(* Logix 5000 project; controller Electronic_Displays vendor 1 type 14 code 65 rev 17.4; software revision 17.01; part 7 of 9 *)
(* tags used below, declared in another part *)
   ENVariable2Message : BOOL;   // 0 = don't setup variable 1 = setup variable
   ENVariable3Message : BOOL;   // 0 = don't setup variable 1 = setup variable
   ENVariable4Message : BOOL;   // 0 = don't setup variable 1 = setup variable
   DN : BOOL;   // Instruction Interface Done Bit
   ER : BOOL;   // Instruction Interface Error Bit
   map_SignOutput : SINT[496];   // Ethernet/IP LEDSIGN.O Data I/O Mapping
   Packet1Sent : STRING;   // The actual packet sent to the sign (Packet1)
   Packet2Sent : STRING;   // The actual packet sent to the sign (Packet2)
   Packet3Sent : STRING;   // The actual packet sent to the sign (Packet3)
   SEQ : DINT;   // Sequence Number
   InCycle : BOOL;   // Incycle
   Error : BOOL;   // Error
   Done : BOOL;   // Done
   SignETX : STRING;   // DO NOT EDIT = ^C
   SignSOH : STRING;   // DO NOT EDIT = ^A
   SignAddress : STRING;
   SignSTX : STRING;   // DO NOT EDIT = ^B
   SignVariable4 : STRING;
   SignVariable3 : STRING;
   SignVariable2 : STRING;
   SignSetMemoryCommand : STRING;   // DO NOT EDIT = SM
   SignCommandCode : STRING;   // DO NOT EDIT = C
   SignSizeVariableCommand : STRING;   // DO NOT EDIT = 0010 (16 bytes of memory) enough for 16 characters
   SignFileVariableCommand : STRING;   // DO NOT EDIT = V
   TotalPacketCount : DINT[7];   // Total Character Count
   Select : DINT;   // Packet Array Select
   PacketMax : DINT;   // Max Packet Count
   Packet3Offset : DINT;
   Packet2Offset : DINT;
   Packet1Offset : DINT;
   Packet : STRING[7];   // Packet Array to send to sign
(* SetupSignVariables, continued *)

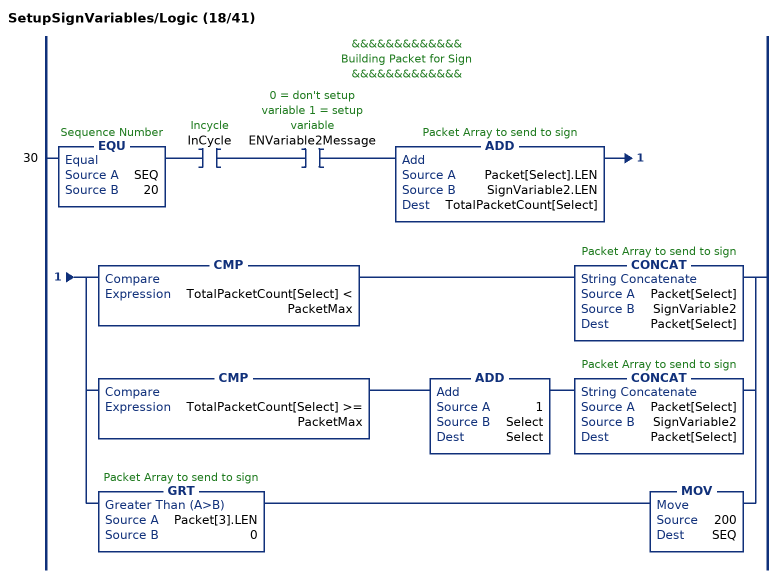
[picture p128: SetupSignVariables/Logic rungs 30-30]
   // &&&&&&&&&&&&&
   // Building Packet for Sign
   // &&&&&&&&&&&&&
   30: EQU(SEQ,20)XIC(InCycle)XIC(ENVariable2Message)ADD(Packet[Select].LEN,SignVariable2.LEN,TotalPacketCount[Select])[CMP(TotalPacketCount[Select] < PacketMax) CONCAT(Packet[Select],SignVariable2,Packet[Select]) ,CMP(TotalPacketCount[Select] >= PacketMax) ADD(1,Select,Select) CONCAT(Packet[Select],SignVariable2,Packet[Select]) ,GRT(Packet[3].LEN,0) MOV(200,SEQ) ];
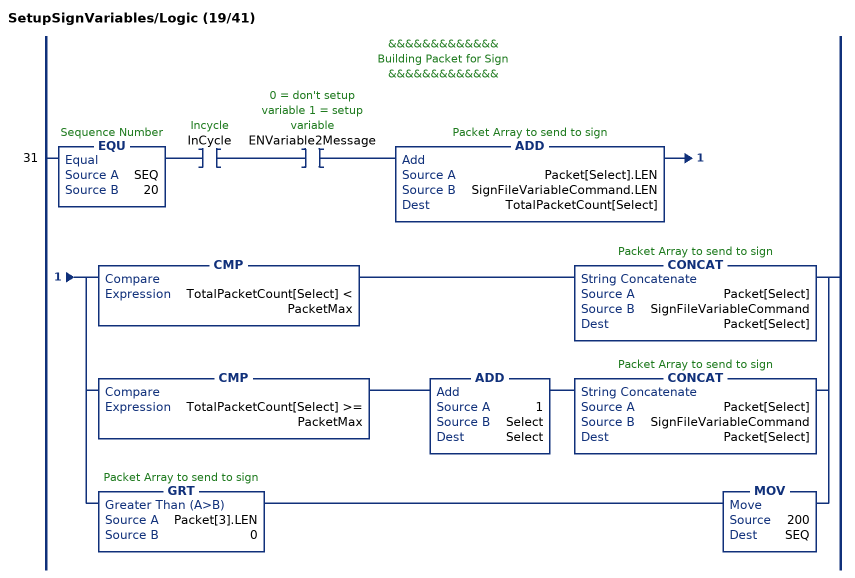
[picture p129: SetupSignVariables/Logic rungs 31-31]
   // &&&&&&&&&&&&&
   // Building Packet for Sign
   // &&&&&&&&&&&&&
   31: EQU(SEQ,20)XIC(InCycle)XIC(ENVariable2Message)ADD(Packet[Select].LEN,SignFileVariableCommand.LEN,TotalPacketCount[Select])[CMP(TotalPacketCount[Select] < PacketMax) CONCAT(Packet[Select],SignFileVariableCommand,Packet[Select]) ,CMP(TotalPacketCount[Select] >= PacketMax) ADD(1,Select,Select) CONCAT(Packet[Select],SignFileVariableCommand,Packet[Select]) ,GRT(Packet[3].LEN,0) MOV(200,SEQ) ];
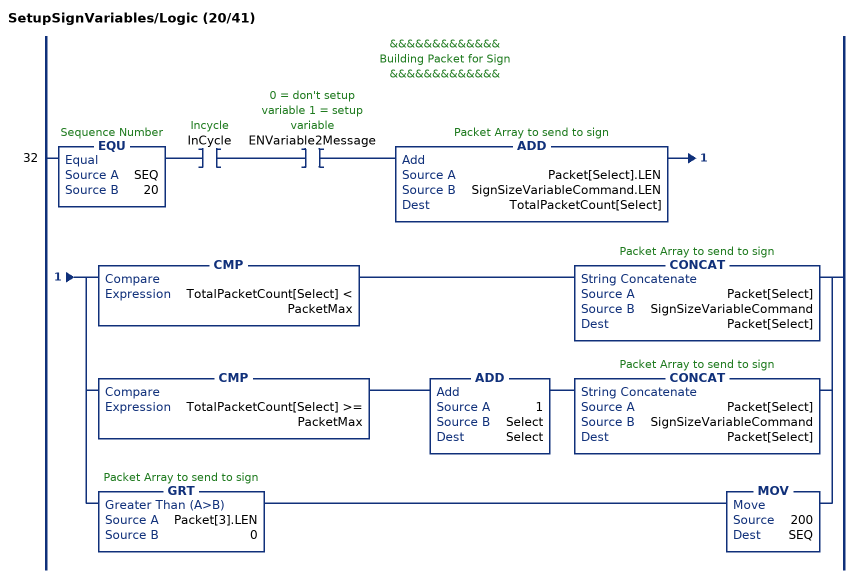
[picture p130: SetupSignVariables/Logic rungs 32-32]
   // &&&&&&&&&&&&&
   // Building Packet for Sign
   // &&&&&&&&&&&&&
   32: EQU(SEQ,20)XIC(InCycle)XIC(ENVariable2Message)ADD(Packet[Select].LEN,SignSizeVariableCommand.LEN,TotalPacketCount[Select])[CMP(TotalPacketCount[Select] < PacketMax) CONCAT(Packet[Select],SignSizeVariableCommand,Packet[Select]) ,CMP(TotalPacketCount[Select] >= PacketMax) ADD(1,Select,Select) CONCAT(Packet[Select],SignSizeVariableCommand,Packet[Select]) ,GRT(Packet[3].LEN,0) MOV(200,SEQ) ];
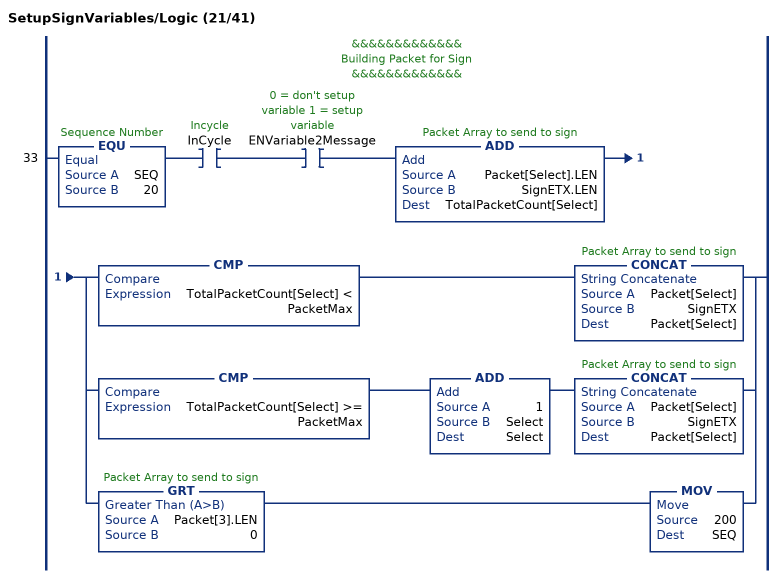
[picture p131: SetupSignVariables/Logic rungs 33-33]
   // &&&&&&&&&&&&&
   // Building Packet for Sign
   // &&&&&&&&&&&&&
   33: EQU(SEQ,20)XIC(InCycle)XIC(ENVariable2Message)ADD(Packet[Select].LEN,SignETX.LEN,TotalPacketCount[Select])[CMP(TotalPacketCount[Select] < PacketMax) CONCAT(Packet[Select],SignETX,Packet[Select]) ,CMP(TotalPacketCount[Select] >= PacketMax) ADD(1,Select,Select) CONCAT(Packet[Select],SignETX,Packet[Select]) ,GRT(Packet[3].LEN,0) MOV(200,SEQ) ];
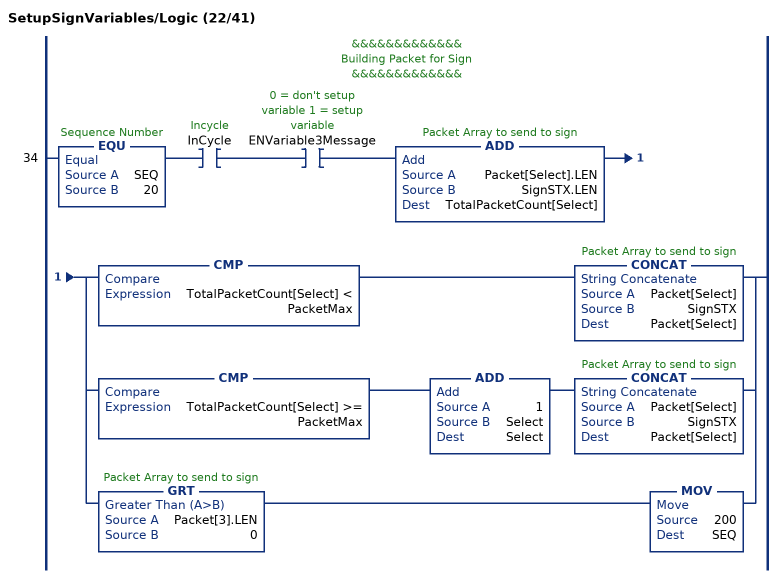
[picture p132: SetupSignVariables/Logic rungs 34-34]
   // &&&&&&&&&&&&&
   // Building Packet for Sign
   // &&&&&&&&&&&&&
   34: EQU(SEQ,20)XIC(InCycle)XIC(ENVariable3Message)ADD(Packet[Select].LEN,SignSTX.LEN,TotalPacketCount[Select])[CMP(TotalPacketCount[Select] < PacketMax) CONCAT(Packet[Select],SignSTX,Packet[Select]) ,CMP(TotalPacketCount[Select] >= PacketMax) ADD(1,Select,Select) CONCAT(Packet[Select],SignSTX,Packet[Select]) ,GRT(Packet[3].LEN,0) MOV(200,SEQ) ];
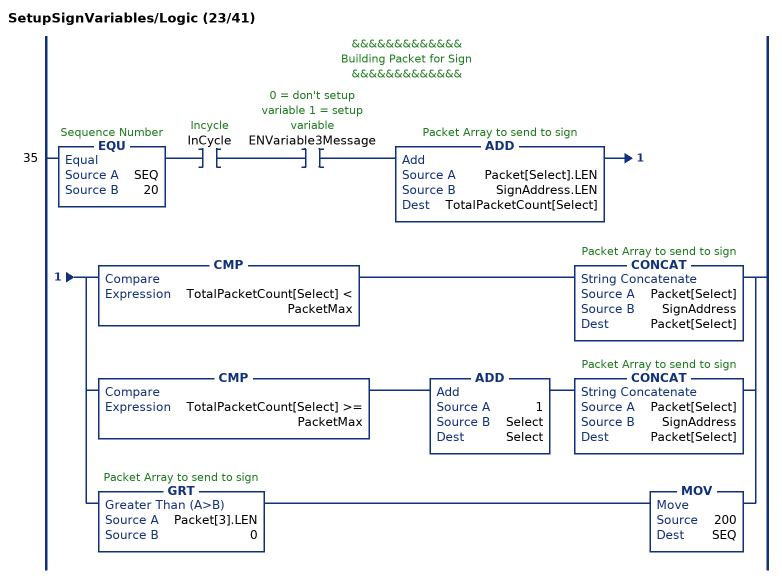
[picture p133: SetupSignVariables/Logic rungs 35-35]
   // &&&&&&&&&&&&&
   // Building Packet for Sign
   // &&&&&&&&&&&&&
   35: EQU(SEQ,20)XIC(InCycle)XIC(ENVariable3Message)ADD(Packet[Select].LEN,SignAddress.LEN,TotalPacketCount[Select])[CMP(TotalPacketCount[Select] < PacketMax) CONCAT(Packet[Select],SignAddress,Packet[Select]) ,CMP(TotalPacketCount[Select] >= PacketMax) ADD(1,Select,Select) CONCAT(Packet[Select],SignAddress,Packet[Select]) ,GRT(Packet[3].LEN,0) MOV(200,SEQ) ];
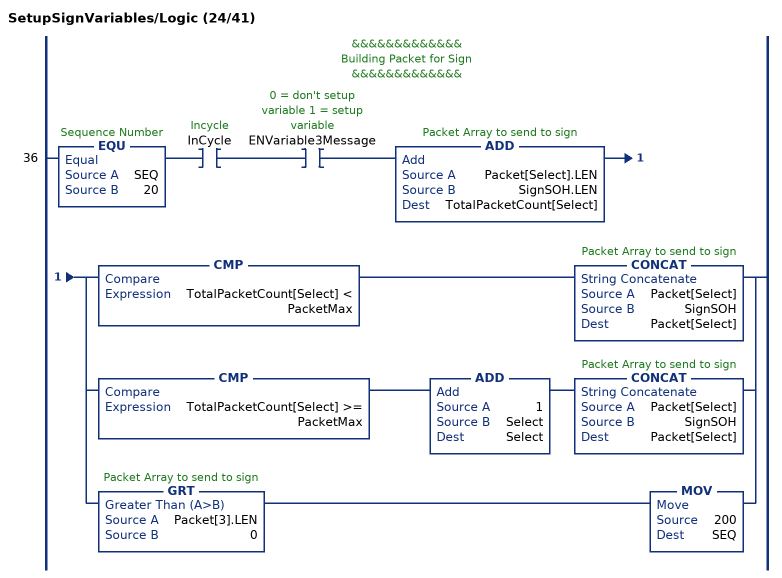
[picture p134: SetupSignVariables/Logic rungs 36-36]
   // &&&&&&&&&&&&&
   // Building Packet for Sign
   // &&&&&&&&&&&&&
   36: EQU(SEQ,20)XIC(InCycle)XIC(ENVariable3Message)ADD(Packet[Select].LEN,SignSOH.LEN,TotalPacketCount[Select])[CMP(TotalPacketCount[Select] < PacketMax) CONCAT(Packet[Select],SignSOH,Packet[Select]) ,CMP(TotalPacketCount[Select] >= PacketMax) ADD(1,Select,Select) CONCAT(Packet[Select],SignSOH,Packet[Select]) ,GRT(Packet[3].LEN,0) MOV(200,SEQ) ];
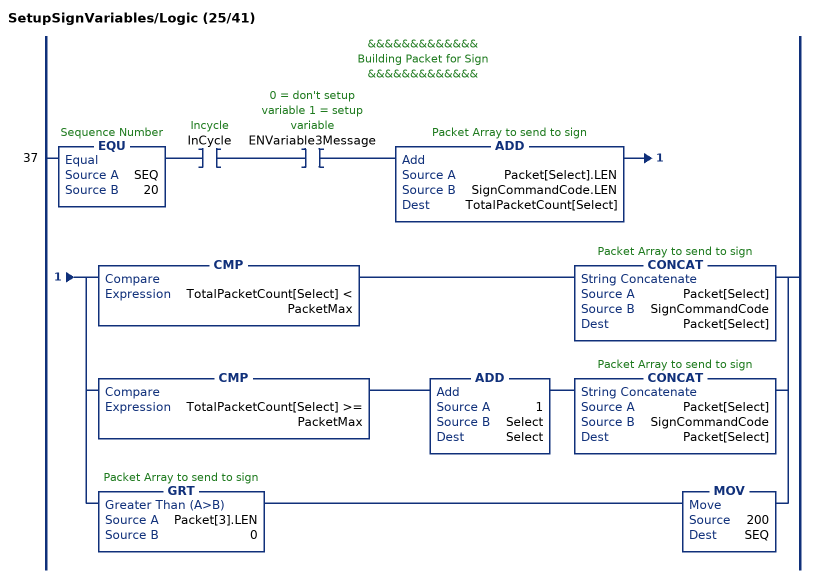
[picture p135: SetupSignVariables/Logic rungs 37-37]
   // &&&&&&&&&&&&&
   // Building Packet for Sign
   // &&&&&&&&&&&&&
   37: EQU(SEQ,20)XIC(InCycle)XIC(ENVariable3Message)ADD(Packet[Select].LEN,SignCommandCode.LEN,TotalPacketCount[Select])[CMP(TotalPacketCount[Select] < PacketMax) CONCAT(Packet[Select],SignCommandCode,Packet[Select]) ,CMP(TotalPacketCount[Select] >= PacketMax) ADD(1,Select,Select) CONCAT(Packet[Select],SignCommandCode,Packet[Select]) ,GRT(Packet[3].LEN,0) MOV(200,SEQ) ];
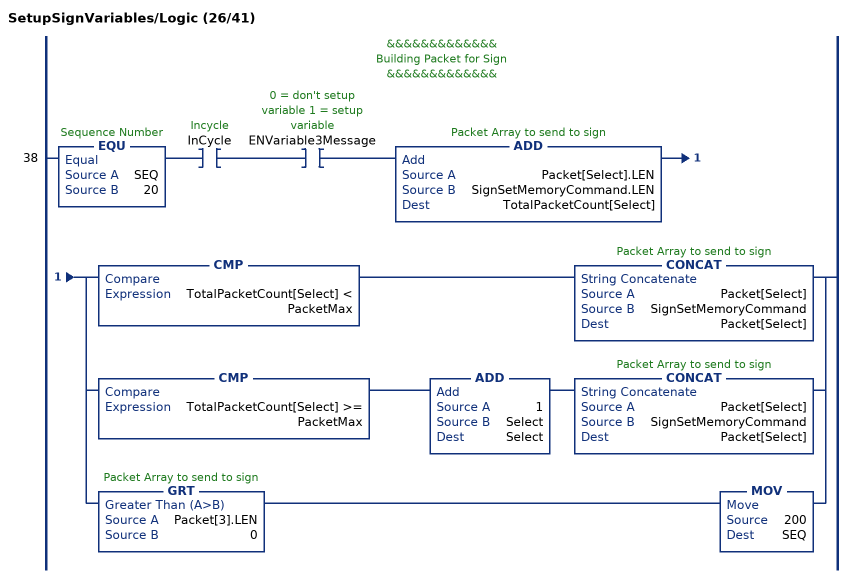
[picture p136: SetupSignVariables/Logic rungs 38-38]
   // &&&&&&&&&&&&&
   // Building Packet for Sign
   // &&&&&&&&&&&&&
   38: EQU(SEQ,20)XIC(InCycle)XIC(ENVariable3Message)ADD(Packet[Select].LEN,SignSetMemoryCommand.LEN,TotalPacketCount[Select])[CMP(TotalPacketCount[Select] < PacketMax) CONCAT(Packet[Select],SignSetMemoryCommand,Packet[Select]) ,CMP(TotalPacketCount[Select] >= PacketMax) ADD(1,Select,Select) CONCAT(Packet[Select],SignSetMemoryCommand,Packet[Select]) ,GRT(Packet[3].LEN,0) MOV(200,SEQ) ];
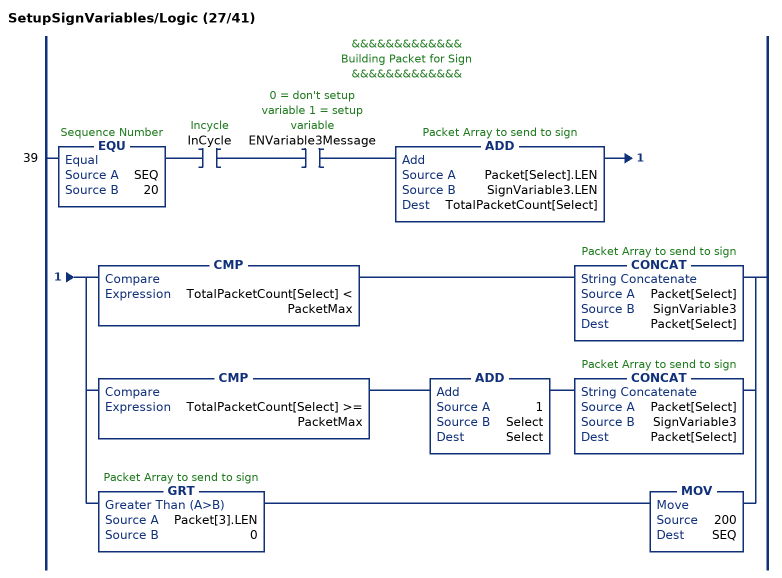
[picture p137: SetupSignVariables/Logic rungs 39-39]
   // &&&&&&&&&&&&&
   // Building Packet for Sign
   // &&&&&&&&&&&&&
   39: EQU(SEQ,20)XIC(InCycle)XIC(ENVariable3Message)ADD(Packet[Select].LEN,SignVariable3.LEN,TotalPacketCount[Select])[CMP(TotalPacketCount[Select] < PacketMax) CONCAT(Packet[Select],SignVariable3,Packet[Select]) ,CMP(TotalPacketCount[Select] >= PacketMax) ADD(1,Select,Select) CONCAT(Packet[Select],SignVariable3,Packet[Select]) ,GRT(Packet[3].LEN,0) MOV(200,SEQ) ];
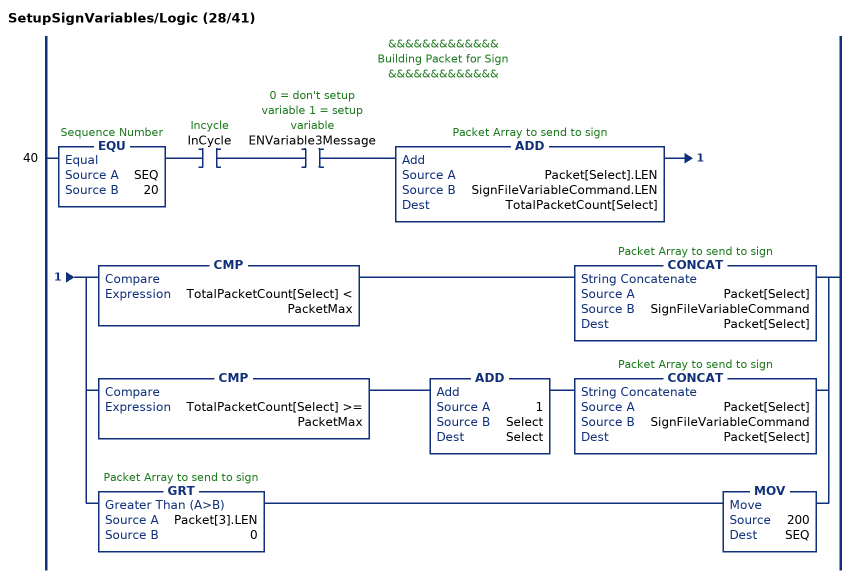
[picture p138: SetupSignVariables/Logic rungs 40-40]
   // &&&&&&&&&&&&&
   // Building Packet for Sign
   // &&&&&&&&&&&&&
   40: EQU(SEQ,20)XIC(InCycle)XIC(ENVariable3Message)ADD(Packet[Select].LEN,SignFileVariableCommand.LEN,TotalPacketCount[Select])[CMP(TotalPacketCount[Select] < PacketMax) CONCAT(Packet[Select],SignFileVariableCommand,Packet[Select]) ,CMP(TotalPacketCount[Select] >= PacketMax) ADD(1,Select,Select) CONCAT(Packet[Select],SignFileVariableCommand,Packet[Select]) ,GRT(Packet[3].LEN,0) MOV(200,SEQ) ];
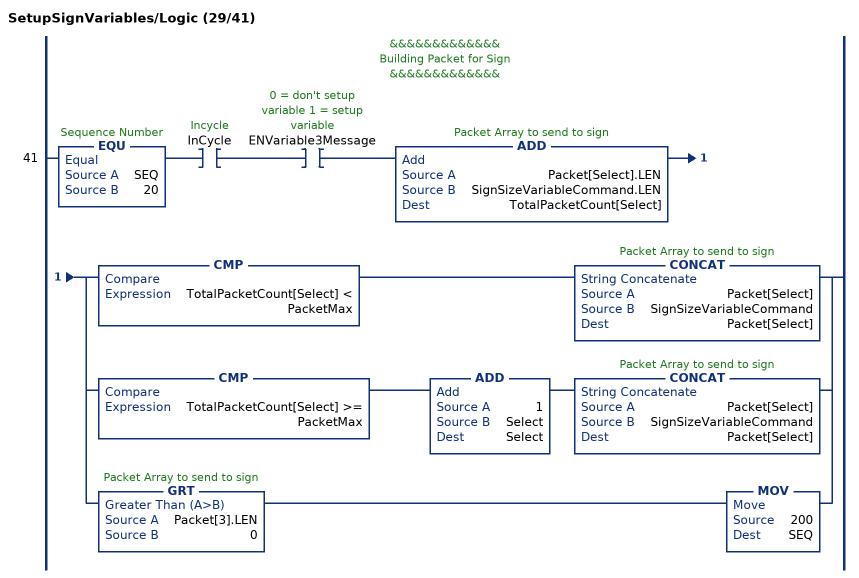
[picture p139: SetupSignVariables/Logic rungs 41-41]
   // &&&&&&&&&&&&&
   // Building Packet for Sign
   // &&&&&&&&&&&&&
   41: EQU(SEQ,20)XIC(InCycle)XIC(ENVariable3Message)ADD(Packet[Select].LEN,SignSizeVariableCommand.LEN,TotalPacketCount[Select])[CMP(TotalPacketCount[Select] < PacketMax) CONCAT(Packet[Select],SignSizeVariableCommand,Packet[Select]) ,CMP(TotalPacketCount[Select] >= PacketMax) ADD(1,Select,Select) CONCAT(Packet[Select],SignSizeVariableCommand,Packet[Select]) ,GRT(Packet[3].LEN,0) MOV(200,SEQ) ];
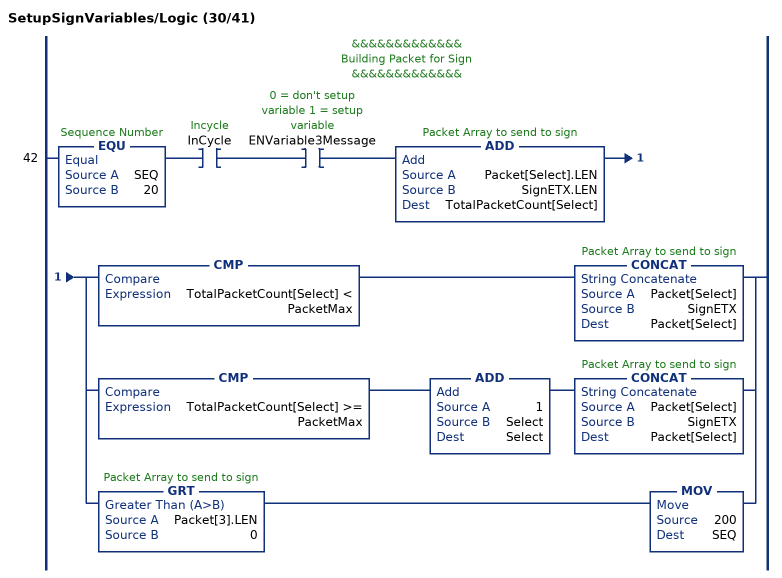
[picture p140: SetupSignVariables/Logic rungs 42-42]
   // &&&&&&&&&&&&&
   // Building Packet for Sign
   // &&&&&&&&&&&&&
   42: EQU(SEQ,20)XIC(InCycle)XIC(ENVariable3Message)ADD(Packet[Select].LEN,SignETX.LEN,TotalPacketCount[Select])[CMP(TotalPacketCount[Select] < PacketMax) CONCAT(Packet[Select],SignETX,Packet[Select]) ,CMP(TotalPacketCount[Select] >= PacketMax) ADD(1,Select,Select) CONCAT(Packet[Select],SignETX,Packet[Select]) ,GRT(Packet[3].LEN,0) MOV(200,SEQ) ];
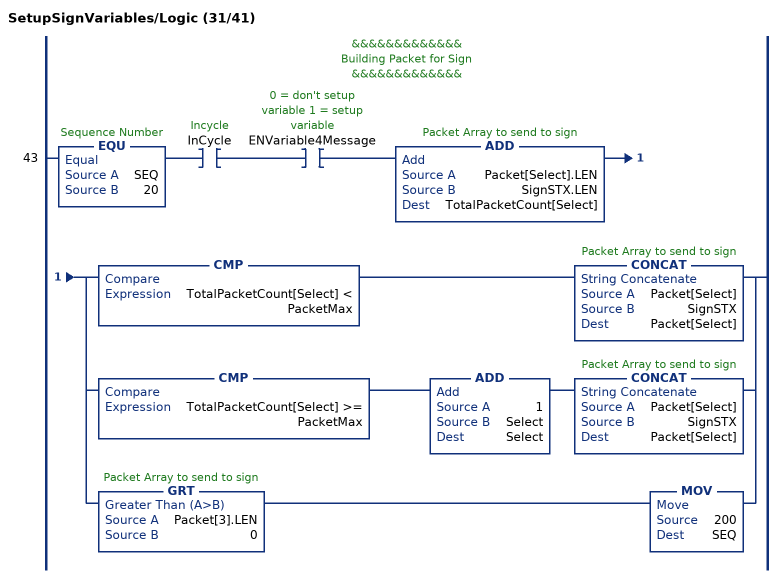
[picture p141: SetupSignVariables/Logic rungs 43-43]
   // &&&&&&&&&&&&&
   // Building Packet for Sign
   // &&&&&&&&&&&&&
   43: EQU(SEQ,20)XIC(InCycle)XIC(ENVariable4Message)ADD(Packet[Select].LEN,SignSTX.LEN,TotalPacketCount[Select])[CMP(TotalPacketCount[Select] < PacketMax) CONCAT(Packet[Select],SignSTX,Packet[Select]) ,CMP(TotalPacketCount[Select] >= PacketMax) ADD(1,Select,Select) CONCAT(Packet[Select],SignSTX,Packet[Select]) ,GRT(Packet[3].LEN,0) MOV(200,SEQ) ];
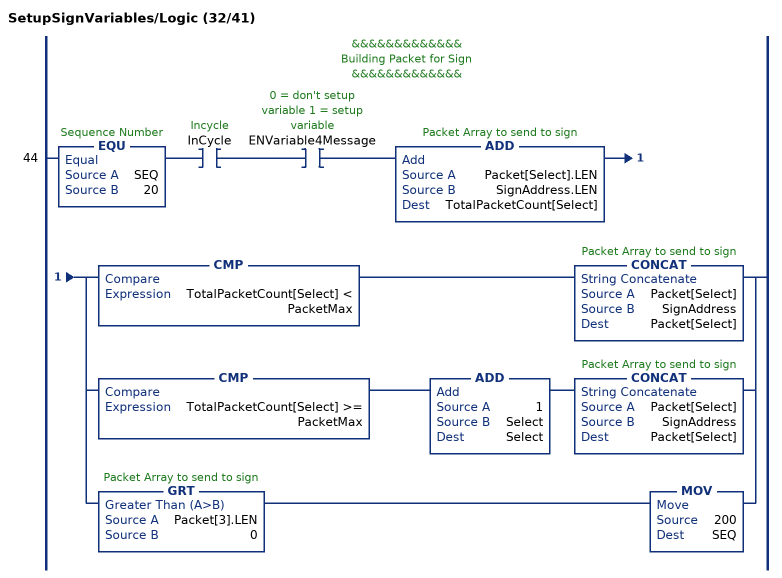
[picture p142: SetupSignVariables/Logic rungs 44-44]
   // &&&&&&&&&&&&&
   // Building Packet for Sign
   // &&&&&&&&&&&&&
   44: EQU(SEQ,20)XIC(InCycle)XIC(ENVariable4Message)ADD(Packet[Select].LEN,SignAddress.LEN,TotalPacketCount[Select])[CMP(TotalPacketCount[Select] < PacketMax) CONCAT(Packet[Select],SignAddress,Packet[Select]) ,CMP(TotalPacketCount[Select] >= PacketMax) ADD(1,Select,Select) CONCAT(Packet[Select],SignAddress,Packet[Select]) ,GRT(Packet[3].LEN,0) MOV(200,SEQ) ];
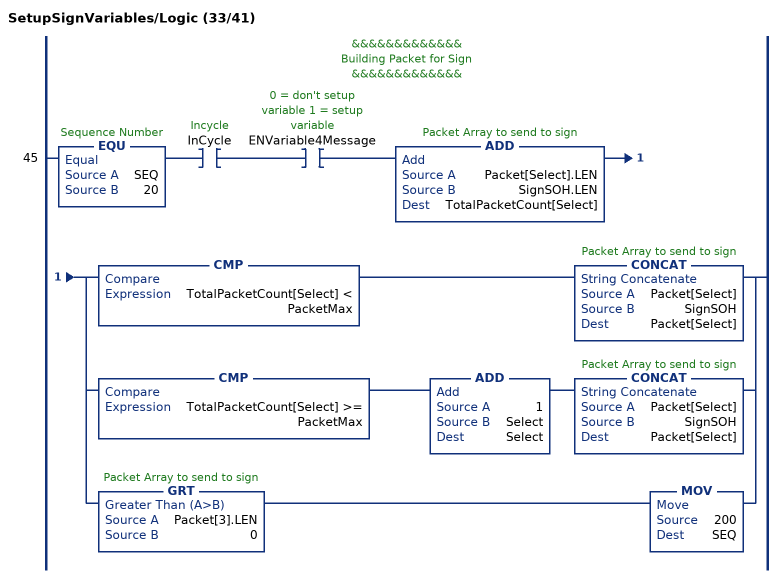
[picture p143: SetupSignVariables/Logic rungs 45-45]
   // &&&&&&&&&&&&&
   // Building Packet for Sign
   // &&&&&&&&&&&&&
   45: EQU(SEQ,20)XIC(InCycle)XIC(ENVariable4Message)ADD(Packet[Select].LEN,SignSOH.LEN,TotalPacketCount[Select])[CMP(TotalPacketCount[Select] < PacketMax) CONCAT(Packet[Select],SignSOH,Packet[Select]) ,CMP(TotalPacketCount[Select] >= PacketMax) ADD(1,Select,Select) CONCAT(Packet[Select],SignSOH,Packet[Select]) ,GRT(Packet[3].LEN,0) MOV(200,SEQ) ];
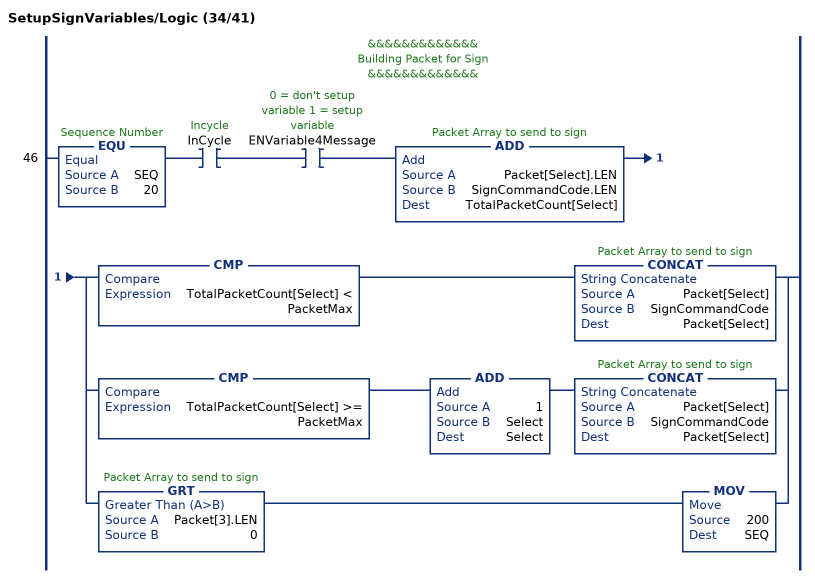
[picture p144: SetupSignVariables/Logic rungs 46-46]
   // &&&&&&&&&&&&&
   // Building Packet for Sign
   // &&&&&&&&&&&&&
   46: EQU(SEQ,20)XIC(InCycle)XIC(ENVariable4Message)ADD(Packet[Select].LEN,SignCommandCode.LEN,TotalPacketCount[Select])[CMP(TotalPacketCount[Select] < PacketMax) CONCAT(Packet[Select],SignCommandCode,Packet[Select]) ,CMP(TotalPacketCount[Select] >= PacketMax) ADD(1,Select,Select) CONCAT(Packet[Select],SignCommandCode,Packet[Select]) ,GRT(Packet[3].LEN,0) MOV(200,SEQ) ];
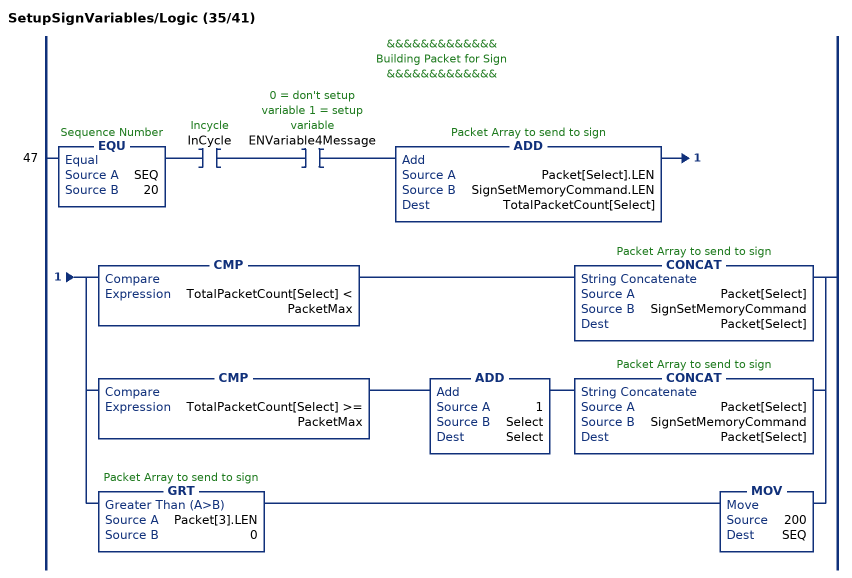
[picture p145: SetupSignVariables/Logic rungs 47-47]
   // &&&&&&&&&&&&&
   // Building Packet for Sign
   // &&&&&&&&&&&&&
   47: EQU(SEQ,20)XIC(InCycle)XIC(ENVariable4Message)ADD(Packet[Select].LEN,SignSetMemoryCommand.LEN,TotalPacketCount[Select])[CMP(TotalPacketCount[Select] < PacketMax) CONCAT(Packet[Select],SignSetMemoryCommand,Packet[Select]) ,CMP(TotalPacketCount[Select] >= PacketMax) ADD(1,Select,Select) CONCAT(Packet[Select],SignSetMemoryCommand,Packet[Select]) ,GRT(Packet[3].LEN,0) MOV(200,SEQ) ];
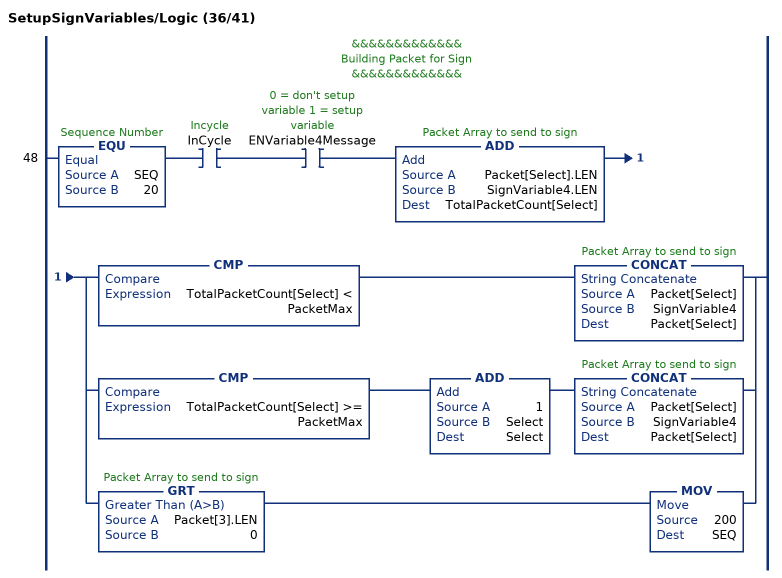
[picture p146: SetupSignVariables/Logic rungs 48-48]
   // &&&&&&&&&&&&&
   // Building Packet for Sign
   // &&&&&&&&&&&&&
   48: EQU(SEQ,20)XIC(InCycle)XIC(ENVariable4Message)ADD(Packet[Select].LEN,SignVariable4.LEN,TotalPacketCount[Select])[CMP(TotalPacketCount[Select] < PacketMax) CONCAT(Packet[Select],SignVariable4,Packet[Select]) ,CMP(TotalPacketCount[Select] >= PacketMax) ADD(1,Select,Select) CONCAT(Packet[Select],SignVariable4,Packet[Select]) ,GRT(Packet[3].LEN,0) MOV(200,SEQ) ];
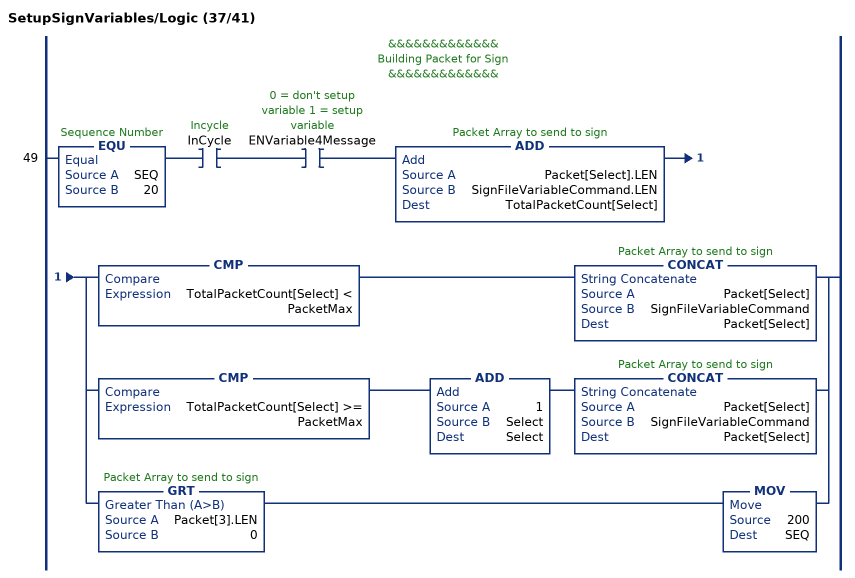
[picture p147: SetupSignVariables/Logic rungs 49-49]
   // &&&&&&&&&&&&&
   // Building Packet for Sign
   // &&&&&&&&&&&&&
   49: EQU(SEQ,20)XIC(InCycle)XIC(ENVariable4Message)ADD(Packet[Select].LEN,SignFileVariableCommand.LEN,TotalPacketCount[Select])[CMP(TotalPacketCount[Select] < PacketMax) CONCAT(Packet[Select],SignFileVariableCommand,Packet[Select]) ,CMP(TotalPacketCount[Select] >= PacketMax) ADD(1,Select,Select) CONCAT(Packet[Select],SignFileVariableCommand,Packet[Select]) ,GRT(Packet[3].LEN,0) MOV(200,SEQ) ];
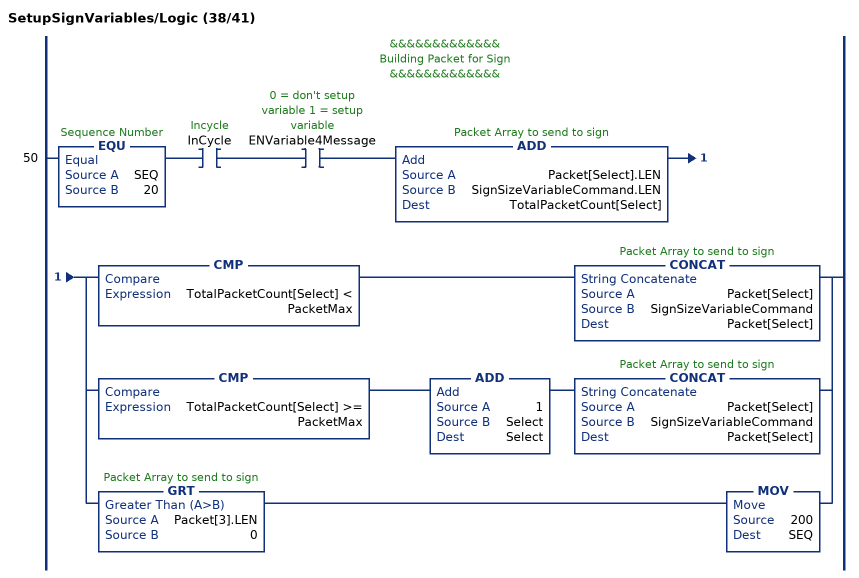
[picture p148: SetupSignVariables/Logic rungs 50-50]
   // &&&&&&&&&&&&&
   // Building Packet for Sign
   // &&&&&&&&&&&&&
   50: EQU(SEQ,20)XIC(InCycle)XIC(ENVariable4Message)ADD(Packet[Select].LEN,SignSizeVariableCommand.LEN,TotalPacketCount[Select])[CMP(TotalPacketCount[Select] < PacketMax) CONCAT(Packet[Select],SignSizeVariableCommand,Packet[Select]) ,CMP(TotalPacketCount[Select] >= PacketMax) ADD(1,Select,Select) CONCAT(Packet[Select],SignSizeVariableCommand,Packet[Select]) ,GRT(Packet[3].LEN,0) MOV(200,SEQ) ];
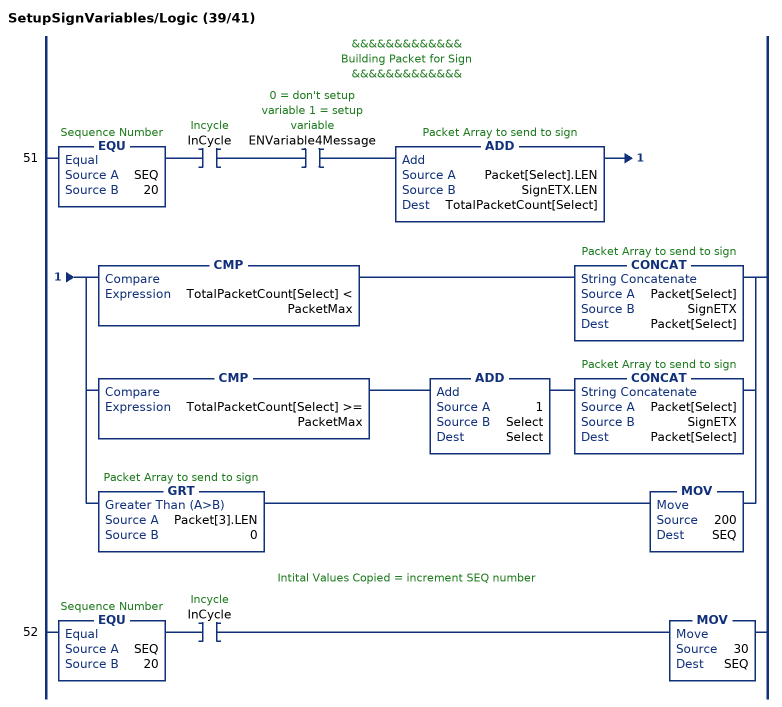
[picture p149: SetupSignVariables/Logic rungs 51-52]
   // &&&&&&&&&&&&&
   // Building Packet for Sign
   // &&&&&&&&&&&&&
   51: EQU(SEQ,20)XIC(InCycle)XIC(ENVariable4Message)ADD(Packet[Select].LEN,SignETX.LEN,TotalPacketCount[Select])[CMP(TotalPacketCount[Select] < PacketMax) CONCAT(Packet[Select],SignETX,Packet[Select]) ,CMP(TotalPacketCount[Select] >= PacketMax) ADD(1,Select,Select) CONCAT(Packet[Select],SignETX,Packet[Select]) ,GRT(Packet[3].LEN,0) MOV(200,SEQ) ];
   // Intital Values Copied = increment SEQ number
   52: EQU(SEQ,20)XIC(InCycle)MOV(30,SEQ);
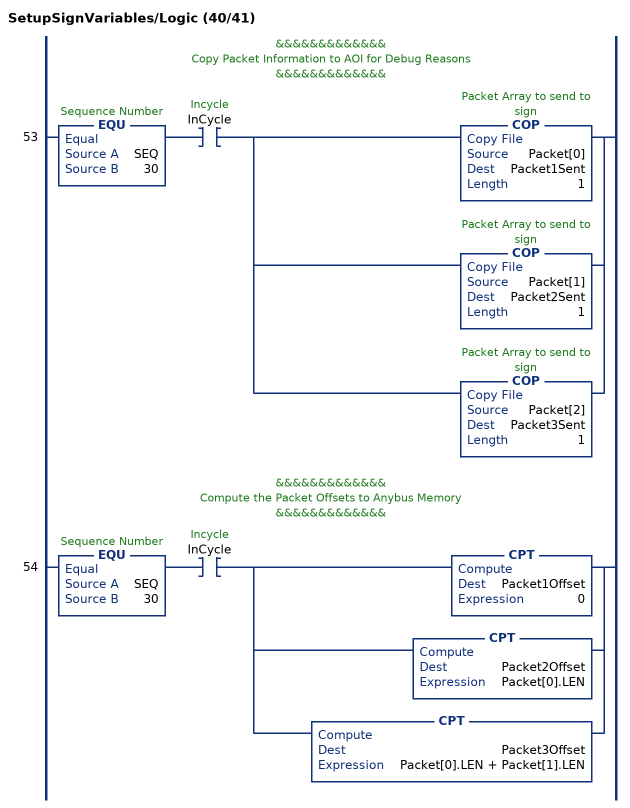
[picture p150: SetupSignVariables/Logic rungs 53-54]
   // &&&&&&&&&&&&&
   // Copy Packet Information to AOI for Debug Reasons
   // &&&&&&&&&&&&&
   53: EQU(SEQ,30)XIC(InCycle)[COP(Packet[0],Packet1Sent,1) ,COP(Packet[1],Packet2Sent,1) ,COP(Packet[2],Packet3Sent,1) ];
   // &&&&&&&&&&&&&
   // Compute the Packet Offsets to Anybus Memory
   // &&&&&&&&&&&&&
   54: EQU(SEQ,30)XIC(InCycle)[CPT(Packet1Offset,0) ,CPT(Packet2Offset,Packet[0].LEN) ,CPT(Packet3Offset,Packet[0].LEN + Packet[1].LEN) ];
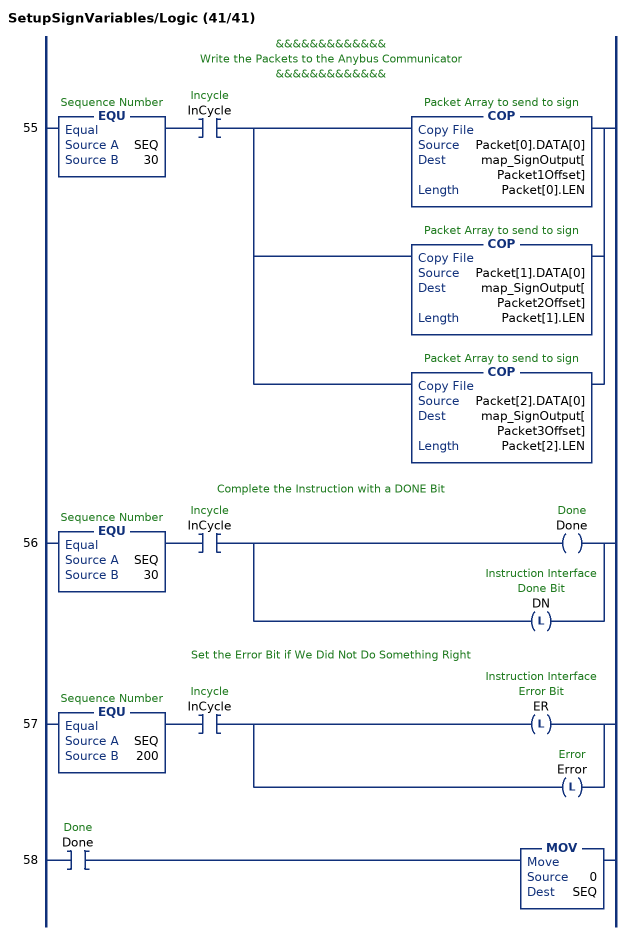
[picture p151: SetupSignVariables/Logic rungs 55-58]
   // &&&&&&&&&&&&&
   // Write the Packets to the Anybus Communicator
   // &&&&&&&&&&&&&
   55: EQU(SEQ,30)XIC(InCycle)[COP(Packet[0].DATA[0],map_SignOutput[Packet1Offset],Packet[0].LEN) ,COP(Packet[1].DATA[0],map_SignOutput[Packet2Offset],Packet[1].LEN) ,COP(Packet[2].DATA[0],map_SignOutput[Packet3Offset],Packet[2].LEN) ];
   // Complete the Instruction with a DONE Bit
   56: EQU(SEQ,30)XIC(InCycle)[OTE(Done) ,OTL(DN) ];
   // Set the Error Bit if We Did Not Do Something Right
   57: EQU(SEQ,200)XIC(InCycle)[OTL(ER) ,OTL(Error) ];
   58: XIC(Done)MOV(0,SEQ);
END_ROUTINE
END_ADD_ON_INSTRUCTION
